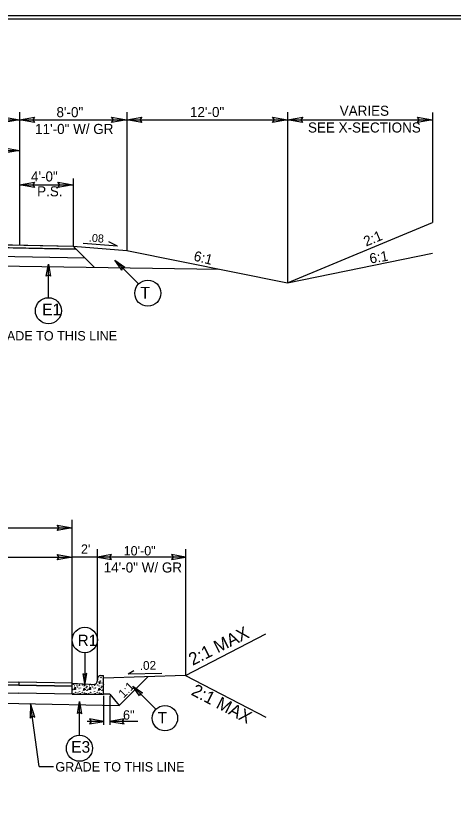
# Model space of a CAD drawing. Extents: x 981824 to 982276, y 44828 to 45204.
# Drawn here: x 982171.98 to 982198.08, y 45040.98 to 45088.17 of the extents above; entities that cross this region are included whole.
import ezdxf

# ---------------------------------------------------------------- set-up
doc = ezdxf.new("R2010")
doc.units = 0
for name, color, linetype in [('Old_Level_1', 7, 'Continuous'), ('Old_Level_11', 7, 'Continuous'), ('Old_Level_18', 7, 'Continuous'), ('Old_Level_2', 7, 'Continuous'), ('Old_Level_20', 7, 'Continuous'), ('Old_Level_21', 7, 'Continuous'), ('Old_Level_3', 7, 'Continuous'), ('Old_Level_50', 7, 'Continuous'), ('Prop Dimension Text', 7, 'Continuous'), ('Typical Terminator CELL', 7, 'Continuous')]:
    doc.layers.add(name, color=color, linetype=linetype)

msp = doc.modelspace()

# ---------------------------------------------------------------- linework, layer by layer
at = {"layer": 'Old_Level_1'}
for p, q in [((982172.194, 45082.429), (982172.194, 45074.486)), ((982178.594, 45082.429), (982178.594, 45074.166)), ((982188.193, 45082.424), (982188.188, 45072.224)), ((982196.843, 45082.396), (982196.843, 45075.824)), ((982157.794, 45081.961), (982172.194, 45081.961)), ((982172.194, 45081.961), (982178.594, 45081.961)), ((982178.594, 45081.961), (982188.194, 45081.961)), ((982188.194, 45081.961), (982196.843, 45081.961)), ((982162.594, 45080.13), (982172.194, 45080.13)), ((982175.392, 45078.468), (982175.392, 45074.422)), ((982172.194, 45078.078), (982175.392, 45078.078)), ((982188.188, 45072.224), (982196.843, 45075.824)), ((982157.794, 45074.774), (982175.392, 45074.422)), ((982178.044, 45074.415), (982177.533, 45074.671)), ((982157.791, 45074.601), (982175.567, 45074.247)), ((982175.392, 45074.422), (982178.594, 45074.166)), ((982175.392, 45074.422), (982176.657, 45073.157)), ((982178.044, 45074.415), (982176.005, 45074.579)), ((982178.594, 45074.166), (982188.188, 45072.224)), ((982157.794, 45074.105), (982176.095, 45073.719)), ((982188.188, 45072.224), (982196.843, 45073.992)), ((982157.794, 45073.422), (982184.096, 45073.052)), ((982175.348, 45048.315), (982175.348, 45058.08)), ((982157.761, 45057.607), (982175.348, 45057.607)), ((982176.843, 45048.451), (982176.843, 45056.322)), ((982162.561, 45055.854), (982175.348, 45055.854)), ((982176.843, 45055.854), (982175.348, 45055.854)), ((982182.108, 45055.854), (982176.843, 45055.854)), ((982182.108, 45048.78), (982186.889, 45051.265)), ((982177.03, 45048.786), (982177.217, 45048.786)), ((982177.217, 45047.665), (982177.217, 45048.786)), ((982182.108, 45048.78), (982186.889, 45046.295)), ((982157.758, 45048.494), (982172.158, 45048.208)), ((982157.761, 45048.667), (982172.161, 45048.379)), ((982172.161, 45048.379), (982172.158, 45048.208)), ((982175.348, 45048.315), (982176.651, 45048.252)), ((982175.348, 45047.665), (982175.348, 45048.315)), ((982157.762, 45048.032), (982172.162, 45047.729)), ((982157.761, 45047.315), (982172.161, 45047.113)), ((982175.348, 45047.665), (982177.217, 45047.665)), ((982177.217, 45047.57), (982177.217, 45045.838)), ((982177.591, 45047.665), (982178.153, 45046.992)), ((982177.591, 45047.576), (982177.591, 45045.838)), ((982172.161, 45047.113), (982178.153, 45046.992)), ((982173.367, 45043.352), (982172.86, 45047.101)), ((982177.221, 45046.042), (982176.227, 45046.042)), ((982179.268, 45046.042), (982177.595, 45046.042)), ((982173.367, 45043.352), (982174.236, 45043.352))]:
    msp.add_line(p, q, dxfattribs=at)
msp.add_lwpolyline([(982172.158, 45048.208), (982175.348, 45048.144), (982175.352, 45048.315), (982172.161, 45048.379)], dxfattribs=at)
for centre, start_param, end_param in [((982177.03, 45048.506), 3.141593, 4.664268), ((982176.657, 45048.533), 6.251273, 7.805861)]:
    msp.add_ellipse(centre, major_axis=(0, -0.28), ratio=0.666667, start_param=start_param, end_param=end_param, dxfattribs=at)
at = {"layer": 'Old_Level_11'}
for p, q in [((982176.094, 45050.146), (982176.094, 45048.19)), ((982180.341, 45046.767), (982178.957, 45048.15))]:
    msp.add_line(p, q, dxfattribs=at)
for points in [[(982173.799, 45072.628), (982173.923, 45073.348), (982174.051, 45072.624), (982173.923, 45072.716)], [(982177.684, 45055.999), (982176.843, 45055.854), (982177.689, 45055.704), (982177.581, 45055.854)], [(982181.267, 45055.709), (982182.108, 45055.854), (982181.263, 45056.003), (982181.37, 45055.854)], [(982175.973, 45048.89), (982176.094, 45048.19), (982176.219, 45048.894), (982176.094, 45048.805)], [(982179.368, 45047.569), (982178.957, 45048.15), (982179.544, 45047.74), (982179.392, 45047.715)], [(982173.116, 45046.287), (982172.86, 45047.101), (982172.825, 45046.243), (982172.959, 45046.37)], [(982175.651, 45046.503), (982175.775, 45047.223), (982175.903, 45046.499), (982175.775, 45046.591)], [(982176.38, 45045.898), (982177.221, 45046.042), (982176.376, 45046.192), (982176.483, 45046.042)], [(982178.436, 45046.187), (982177.595, 45046.042), (982178.441, 45045.893), (982178.333, 45046.042)]]:
    msp.add_lwpolyline(points, close=True, dxfattribs=at)
for centre in [(982176.094, 45050.902), (982180.876, 45046.232)]:
    msp.add_circle(centre, 0.757, dxfattribs=at)
at = {"layer": 'Old_Level_18'}
msp.add_lwpolyline([(982227.72, 45087.969), (982107.72, 45087.969), (982107.72, 45003.969), (982227.72, 45003.969)], close=True, dxfattribs=at)
at = {"layer": 'Old_Level_2'}
for p, q in [((982182.108, 45056.322), (982182.108, 45048.78)), ((982178.682, 45048.875), (982179.021, 45049.08)), ((982178.682, 45048.875), (982180.699, 45048.916)), ((982176.931, 45048.408), (982176.943, 45048.311)), ((982177.041, 45048.36), (982176.931, 45048.408)), ((982176.943, 45048.311), (982177.041, 45048.36)), ((982175.46, 45047.949), (982175.522, 45048.078)), ((982175.547, 45047.955), (982175.46, 45047.949)), ((982175.522, 45048.078), (982175.547, 45047.955)), ((982176.01, 45047.894), (982176.055, 45048.017)), ((982176.129, 45047.936), (982176.01, 45047.894)), ((982176.055, 45048.017), (982176.129, 45047.936)), ((982176.357, 45047.949), (982176.419, 45048.078)), ((982176.443, 45047.955), (982176.357, 45047.949)), ((982176.419, 45048.078), (982176.443, 45047.955)), ((982176.906, 45047.894), (982176.951, 45048.017)), ((982177.025, 45047.936), (982176.906, 45047.894)), ((982176.951, 45048.017), (982177.025, 45047.936))]:
    msp.add_line(p, q, dxfattribs=at)
for centre in [(982176.902, 45048.686), (982175.415, 45048.256), (982175.518, 45048.274), (982175.624, 45048.206), (982175.772, 45048.189), (982175.784, 45048.243), (982175.968, 45048.213), (982176.312, 45048.256), (982176.521, 45048.206), (982176.668, 45048.189), (982176.681, 45048.243), (982176.828, 45048.483), (982176.865, 45048.213), (982177.021, 45048.452), (982177.058, 45048.649), (982177.115, 45048.336), (982177.188, 45048.575), (982177.208, 45048.256), (982175.395, 45047.949), (982175.485, 45048.164), (982175.547, 45047.771), (982175.645, 45048.097), (982175.694, 45047.746), (982175.751, 45048.005), (982175.776, 45047.839), (982175.842, 45048.035), (982175.944, 45047.783), (982176.055, 45048.158), (982176.067, 45047.74), (982176.177, 45047.722), (982176.182, 45048.054), (982176.194, 45048.158), (982176.222, 45047.9), (982176.234, 45048.121), (982176.291, 45047.949), (982176.382, 45048.164), (982176.443, 45047.771), (982176.541, 45048.097), (982176.59, 45047.746), (982176.648, 45048.005), (982176.672, 45047.839), (982176.738, 45048.035), (982176.84, 45047.783), (982176.951, 45048.158), (982176.963, 45047.74), (982177.074, 45047.722), (982177.078, 45048.054), (982177.09, 45048.158), (982177.119, 45047.9), (982177.131, 45048.121), (982177.188, 45047.949), (982175.432, 45047.697), (982175.817, 45047.716), (982176.328, 45047.697), (982176.713, 45047.716), (982177.225, 45047.697)]:
    msp.add_ellipse(centre, major_axis=(0, 0.00863), ratio=0.666667, dxfattribs=at)
msp.add_ellipse((982176.414, 45048.274), major_axis=(0, 0.00863), ratio=0.666667, start_param=1.410869, end_param=4.788971, dxfattribs=at)
at = {"layer": 'Old_Level_21'}
for points in [[(982162.594, 45074.678), (982175.392, 45074.422), (982175.567, 45074.247), (982162.591, 45074.505)], [(982162.561, 45048.571), (982172.161, 45048.379), (982172.158, 45048.208), (982162.558, 45048.398)]]:
    msp.add_lwpolyline(points, close=True, dxfattribs=at)
at = {"layer": 'Old_Level_3'}
for p, q in [((982182.108, 45048.78), (982177.217, 45048.629)), ((982178.153, 45046.992), (982179.881, 45048.721)), ((982175.348, 45048.144), (982172.158, 45048.208)), ((982175.348, 45048.315), (982172.159, 45048.379)), ((982175.348, 45047.665), (982172.162, 45047.729)), ((982177.591, 45047.665), (982177.217, 45047.665))]:
    msp.add_line(p, q, dxfattribs=at)
at = {"layer": 'Old_Level_50'}
msp.add_lwpolyline([(982228.72, 45088.173), (982095.4, 45088.173), (982095.4, 45003.765), (982228.72, 45003.765)], close=True, dxfattribs=at)
at = {"layer": 'Prop Dimension Text'}
for p, q in [((982173.923, 45071.339), (982173.923, 45073.348)), ((982179.304, 45072.161), (982177.882, 45073.582)), ((982175.775, 45045.213), (982175.775, 45047.223))]:
    msp.add_line(p, q, dxfattribs=at)
for centre in [(982179.854, 45071.611), (982173.923, 45070.561), (982175.774, 45044.435)]:
    msp.add_circle(centre, 0.778, dxfattribs=at)
at = {"layer": 'Typical Terminator CELL'}
for points in [[(982171.294, 45082.116), (982172.194, 45081.961), (982171.289, 45081.801), (982171.404, 45081.961)], [(982173.094, 45081.806), (982172.194, 45081.961), (982173.099, 45082.121), (982172.984, 45081.961)], [(982177.694, 45082.116), (982178.594, 45081.961), (982177.689, 45081.801), (982177.804, 45081.961)], [(982179.494, 45081.806), (982178.594, 45081.961), (982179.499, 45082.121), (982179.384, 45081.961)], [(982187.294, 45082.116), (982188.194, 45081.961), (982187.289, 45081.801), (982187.404, 45081.961)], [(982189.094, 45081.806), (982188.194, 45081.961), (982189.099, 45082.121), (982188.984, 45081.961)], [(982195.943, 45082.116), (982196.843, 45081.961), (982195.938, 45081.801), (982196.053, 45081.961)], [(982171.294, 45080.285), (982172.194, 45080.13), (982171.289, 45079.97), (982171.404, 45080.13)], [(982173.094, 45077.923), (982172.194, 45078.078), (982173.099, 45078.238), (982172.984, 45078.078)], [(982174.492, 45078.233), (982175.392, 45078.078), (982174.487, 45077.918), (982174.602, 45078.078)], [(982178.304, 45072.985), (982177.882, 45073.582), (982178.485, 45073.16), (982178.329, 45073.135)], [(982174.448, 45057.762), (982175.348, 45057.607), (982174.443, 45057.447), (982174.558, 45057.607)], [(982174.448, 45056.009), (982175.348, 45055.854), (982174.443, 45055.694), (982174.558, 45055.854)]]:
    msp.add_lwpolyline(points, close=True, dxfattribs=at)

# ---------------------------------------------------------------- texts
at = {"layer": 'Old_Level_1'}
for s, p in [('8\'-0"', (982174.404, 45082.12)), ('12\'-0"', (982182.37, 45082.129)), ('VARIES', (982191.304, 45082.204)), ('11\'-0" W/ GR', (982173.13, 45081.118)), ('SEE X-SECTIONS', (982189.411, 45081.204)), ('4\'-0"', (982172.883, 45078.281)), ('P.S.', (982173.249, 45077.393)), ('14\'-0" W/ GR', (982177.223, 45054.932))]:
    msp.add_text(s, height=0.6, dxfattribs=at).set_placement(p)
for s, height, rotation, p in [('2:1', 0.6, 22.5828, (982192.88, 45074.391)), ('6:1', 0.6, 345.9638, (982182.551, 45073.568)), ('6:1', 0.6, 9.4617, (982193.134, 45073.375)), ("2'", 0.5606, 360, (982175.865, 45056.05)), ('10\'-0"', 0.5606, 360, (982178.413, 45055.949)), ('2:1 MAX', 0.75, 26.5646, (982182.527, 45049.353)), ('.02', 0.5232, 1.1458, (982179.38, 45049.111)), ('2:1 MAX', 0.75, 332.6161, (982182.388, 45047.65)), ('6"', 0.5606, 360, (982178.376, 45046.145))]:
    msp.add_text(s, height=height, rotation=rotation, dxfattribs=at).set_placement(p)
at = {"layer": 'Old_Level_2'}
msp.add_text('.08', height=0.48, rotation=355.4261, dxfattribs=at).set_placement((982176.324, 45074.694))
at = {"layer": 'Old_Level_20'}
for s, p in [('T ', (982179.412, 45071.292)), ('E1', (982173.551, 45070.296)), ('E3', (982175.28, 45044.171))]:
    msp.add_text(s, height=0.696, dxfattribs=at).set_placement(p)
for s, p in [('R1', (982175.672, 45050.542)), ('T ', (982180.445, 45045.92))]:
    msp.add_text(s, height=0.6774, rotation=360, dxfattribs=at).set_placement(p)
at = {"layer": 'Old_Level_3'}
for s, height, rotation, p in [('GRADE TO THIS LINE', 0.56063, 360, (982170.319, 45068.786)), ('1:1', 0.5233, 45, (982178.412, 45047.398)), ('GRADE TO THIS LINE', 0.56063, 360, (982174.34, 45043.049))]:
    msp.add_text(s, height=height, rotation=rotation, dxfattribs=at).set_placement(p)

doc.saveas('drawing.dxf')
